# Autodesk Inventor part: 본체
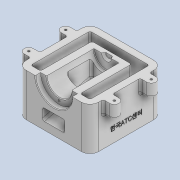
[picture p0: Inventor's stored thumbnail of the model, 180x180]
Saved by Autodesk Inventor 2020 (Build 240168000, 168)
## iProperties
Created: 2022-03
Part Number: 본체
Material: 일반
Document SubType Name: Modeling
Designer: Administrator
Density: 1 g/cm^3
Appearance: 기본값
Author: Administrator
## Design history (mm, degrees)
sketch "스케치1"
  geometry: L1 (-55, 55)-(55, 55); L2 (55, 55)-(55, -55); L3 (55, -55)-(-55, -55); L4 (-55, -55)-(-55, 55); L5 (-55, 55)-(55, -55); L6 (55, 55)-(-55, -55); 1 further point
  constraints: 12 end point, 2 midpoint, 2 parallel, 1 horizontal, 1 perpendicular
  dimensions: "d0" = 110 distance of L1.start L1.end; "d1" = 110 distance of L3.end L1.start
extrude "돌출1" new body sketch "스케치1" distance "d2" = 65; taper "d3" = 0 deg
fillet "모깎기1" dims "d4" = 13
feature "쉘1" dims "d5" = 10
sketch "스케치3"
  geometry: L1 (-55, 0)-(-55, 65) reference; L2 (-55, 65)-(60.016, 65); L3 (33, 65)-(33, 30); L4 (55, 65)-(55, 0) reference; L5 (-55, 6.42)-(33, 30); L6 (-45, 0)-(-45, 65) reference; L7 (42, 0)-(-42, 0) reference; 2 further points
  constraints: 6 end point, 4 point on line, 1 horizontal, 1 vertical
  dimensions: "d14" = 22 distance between parallel lines of L3 L4; "d15" = 75 deg angle of L3 L5; "d19" = 30 distance from line of L3.end L7
sketch "스케치2"
  geometry: L1 (-55, 0)-(-55, 65) reference; L2 (-55, 65)-(69.829, 65); L3 (-55, 65)-(-55, 93); L4 (-55, 93)-(-47, 93); L5 (-47, 93)-(-47, 84); L6 (-47, 84)-(25, 84); L7 (25, 84)-(25, 72.5); L8 (25, 72.5)-(29, 70.191); L9 (29, 70.191)-(29, 65); 1 further point
  constraints: 16 end point, 4 perpendicular, 1 horizontal, 1 parallel, 1 point on line, 1 vertical
  dimensions: "d6" = 56 diameter of L4 L2; "d7" = 38 diameter of L6 L2; "d8" = 30 deg angle of L8 L2; "d10" = 15 diameter of L7.end L2; "d11" = 8 distance of L3.end L4.end; "d12" = 72 distance of L5.end L6.end; "d13" = 4 horizontal distance of L7.end L8.end
extrude "돌출2" join sketch "스케치3" stored distance "d20" = 60; taper "d21" = 0 deg
revolve "회전3" stored, may be unused: angle "d22" = 90 deg
sketch "스케치4"
  geometry: L1 (33, 30)-(-45, 9.1) reference; L2 (19, 31.425)-(-55, 11.597); L3 (-55, 37)-(-55, 65) reference; L4 (-55, 0)-(-55, 65) reference; L5 (25, 46)-(-47, 46) reference; L6 (-19, 38.843)-(-55, 29.197); L7 (-19, 65)-(-19, 38.843); L8 (19, 65)-(19, 31.425); L9 (-47, 65)-(25, 65) reference; 3 further points
  constraints: 8 end point, 8 point on line, 3 parallel, 1 vertical
  dimensions: "d23" = 5 distance between parallel lines of L2 L1; "d27" = 36 distance between parallel lines of L7 L4; "d28" = 38 distance between parallel lines of L8 L7; "d29" = 17 distance between parallel lines of L6 L2
extrude "돌출3" cut sketch "스케치4" stored distance "d30" = 34; taper "d31" = 0 deg
sketch "스케치5"
  geometry: L1 (-65, -35)-(-45, -35); L2 (-45, -35)-(-45, -21); L3 (-45, -21)-(-65, -21); L4 (-65, -21)-(-65, -35); L5 (42, 55)-(-42, 55) reference; L6 (-45, -42)-(-45, 42) reference; L7 (0, 55)-(0, -68.794); L8 (-45, 0)-(-112.804, 0); L9 (-45, 21)-(-65, 21); L10 (-65, 35)-(-45, 35); L11 (-45, 35)-(-45, 21); C1 r 7 at (-65, -28); C2 r 7 at (-65, 28); 8 further points
  constraints: 18 end point, 5 symmetric about line, 3 midpoint, 2 centre point, 2 horizontal, 2 parallel, 1 coincident, 1 collinear, 1 perpendicular, 1 tangent, 1 vertical, 1 other
  dimensions: "d32" = 83 distance from line of C1.centre L5; "d33" = 14 distance of L1.end L2.end; "d34" = 65 distance from line of C2.centre L7; "d37" = 27 distance from line of C2.centre L5 (derived)
extrude "돌출4" join sketch "스케치5" distance "d35" = 20; taper "d36" = 0 deg
sketch "스케치6"
  geometry: A1 r 7 centre (-65, 28) between (-65, 35) and (-65, 21) reference; A2 r 7 centre (-65, -28) between (-65, -21) and (-65, -35) reference; A3 r 7 centre (65, -28) between (65, -35) and (65, -21) reference; A4 r 7 centre (65, 28) between (65, 21) and (65, 35) reference; 5 further points
  constraints: 4 coincident
hole "구멍1" sketch "스케치6" at (-65, 28), (-65, -28), (65, -28), (65, 28) diameter "d38" = 3.242; stored, may be unused: countersink angle "d42" = 90 deg, drill point angle "d44" = 118 deg; dims "d39" = 9, "d40" = 26, "d41" = 10, "d43" = 11
sketch "스케치7"
  geometry: L1 (19, 0)-(28, 0) reference; L2 (-28, 0)-(-19, 0) reference; A1 r 19 centre (0, 0) between (-19, 0) and (19, 0) reference; A2 r 28 centre (0, 0) between (-28, 0) and (28, 0) reference; 2 further points
  constraints: 1 vertical alignment
  dimensions: "d45" = 23 distance of A1.centre point (0, -23)
hole "구멍2" sketch "스케치7" at (0, -23) diameter "d46" = 3.242; stored, may be unused: countersink angle "d50" = 90 deg, drill point angle "d52" = 118 deg; dims "d47" = 9, "d48" = 26, "d49" = 10, "d51" = 11
chamfer "모따기1" distance "d53" = 1; stored, may be unused: second distance "d54" = 2, angle "d55" = 45 deg
fillet "모깎기2" dims "d56" = 3, "d57" = 1
sketch "스케치8"
  geometry: L1 (-65, -13)-(0, -13) reference; 2 further points
  constraints: 1 other
  dimensions: "d58" = 55 distance from line of point (-20, 42) L1; "d59" = 20 distance of point (-20, 42) point (0, 42)
feature "엠보싱1" sketch "스케치8" dims "d60" = 0.5, "d61" = 0
fillet "모깎기3" dims "d62" = 3
node "솔리드1"
mirror "미러1"
node "투영된 루프1"
feature "A9D066F2-1C7D-4E18-AEED-F7BC21143FA4" dims "d38" = 3.242, "d39" = 9, "d40" = 26, "d41" = 10, "d42" = 90 deg, "d43" = 11, "d44" = 118 deg
other parameters: "d24" = 17, "d25" = 36, "d26" = 38
